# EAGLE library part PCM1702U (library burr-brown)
BiCMOS Advanced Sign Magnitude 20-Bit DAC
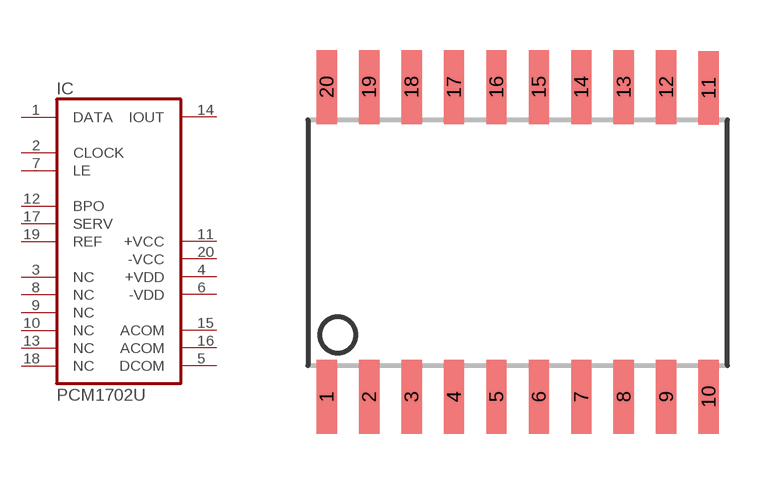
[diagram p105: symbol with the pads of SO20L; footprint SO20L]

Designator prefix IC

## PCM1702U (MF: TEXAS INSTRUMENT CONNECTORS; MPN: PCM1702U; OC_FARNELL: 1509914; OC_NEWARK: 75C5299)  [SO20L]
1  DATA  in
2  CLOCK  in
3  NC  nc
4  +VDD  pwr
5  DCOM  pwr
6  -VDD  pwr
7  LE  in
8  NC  nc
9  NC  nc
10  NC  nc
11  +VCC  pwr
12  BPO  pas
13  NC  nc
14  IOUT  out
15  ACOM  pwr
16  ACOM  pwr
17  SERV  pas
18  NC  nc
19  REF  pas
20  -VCC  pwr

## Footprint SO20L (pad centres in mm)
Small Outline Package, large
smd 0.61 x 2.21: 1 -5.715,-4.636; 2 -4.445,-4.636; 3 -3.175,-4.636; 4 -1.905,-4.636; 5 -0.635,-4.636; 6 0.635,-4.636; 7 1.905,-4.636; 8 3.175,-4.636; 9 4.445,-4.636; 10 5.715,-4.636; 11 5.715,4.61; 12 4.445,4.636; 13 3.175,4.636; 14 1.905,4.636; 15 0.635,4.636; 16 -0.635,4.636; 17 -1.905,4.636; 18 -3.175,4.636; 19 -4.445,4.636; 20 -5.715,4.636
